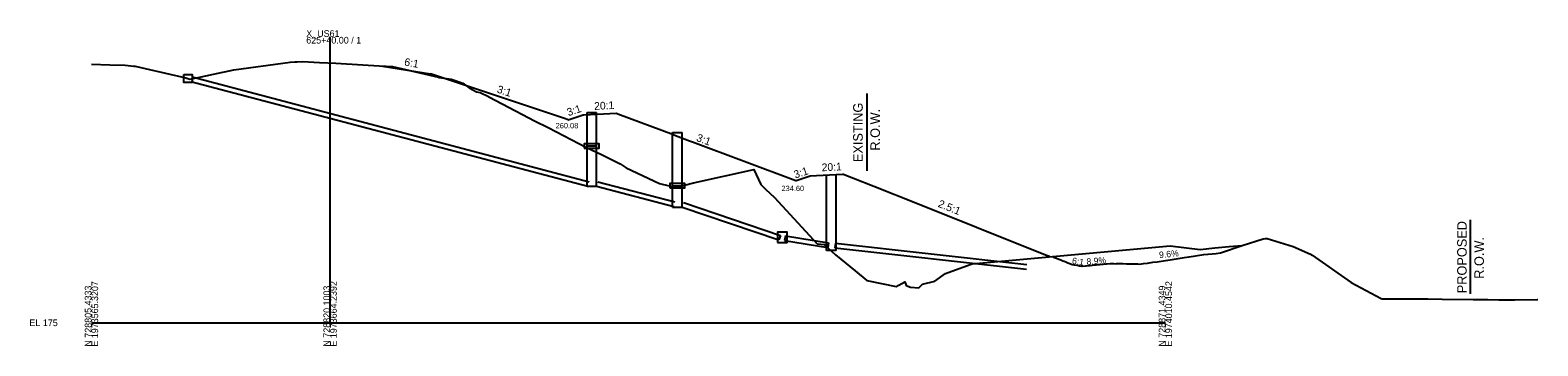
# Model space of a CAD drawing. Extents: x -26 to 630, y -39 to 9098.
# Drawn here: x -26 to 606, y 3490 to 3623 of the extents above; entities that cross this region are included whole.
import ezdxf

# ---------------------------------------------------------------- set-up
doc = ezdxf.new("R2010")
doc.units = 0
for name, color, linetype in [('CONST_DCH', 7, 'Continuous'), ('Default', 7, 'Continuous'), ('Draft_XS_Grid', 7, 'Continuous'), ('DTM_X_FLOW_ARROWS', 7, 'Continuous'), ('DTM_X_GROUND', 7, 'Continuous'), ('X_DTM_CONTOURS_MAJOR', 7, 'Continuous'), ('XS_CELL', 7, 'Continuous'), ('XS_P_DRAINAGE', 7, 'Continuous'), ('XS_P_GROUND', 7, 'Continuous'), ('XS_P_ROW', 7, 'Continuous'), ('XS_P_TX_DCH', 7, 'Continuous'), ('XS_P_TX_FS_BS', 7, 'Continuous'), ('XS_X_DRAINAGE', 7, 'Continuous'), ('XS_X_ROW', 7, 'Continuous')]:
    doc.layers.add(name, color=color, linetype=linetype)

msp = doc.modelspace()

# ---------------------------------------------------------------- linework, layer by layer
at = {"layer": 'DTM_X_GROUND'}
msp.add_lwpolyline([(0, 3608.6), (0.08, 3608.6), (7.63, 3608.32), (14.14, 3608.09), (17.77, 3607.77), (18.26, 3607.73), (22.45, 3606.73), (39.49, 3602.78), (41.19, 3602.23), (44.75, 3602.99), (51.16, 3604.35), (59.69, 3606.16), (83.26, 3609.39), (85.24, 3609.56), (86.23, 3609.58), (88.53, 3609.64), (95.49, 3609.29), (102.44, 3608.93), (122.82, 3607.7), (123.39, 3607.67), (123.52, 3607.66), (126.07, 3607.6), (129.7, 3606.68), (145.37, 3603.06), (145.43, 3603.03), (145.67, 3603.02), (150.72, 3602.29), (151.57, 3601.99), (152.45, 3601.67), (153.29, 3601.37), (153.95, 3601.13), (154.49, 3600.94), (154.79, 3600.83), (155.34, 3600.63), (155.58, 3600.55), (158.25, 3598.64), (161.31, 3596.96), (162.88, 3596.69), (166.36, 3594.97), (166.54, 3594.89), (183.33, 3585.99), (185.59, 3584.82), (191.42, 3581.9), (207.41, 3573.64), (213.7, 3570.65), (221.51, 3566.72), (223.98, 3565), (238.07, 3558.47), (242.09, 3557.45), (243.18, 3557.22), (244.66, 3556.84), (252.33, 3558.72), (277.57, 3564.38), (280.48, 3558.05), (282.44, 3556.15), (286.26, 3552.63), (304.1, 3533.11), (307.01, 3532.84), (311.83, 3528.55), (319.96, 3521.82), (324.91, 3517.73), (337.14, 3515.29), (338.15, 3515.8), (338.22, 3515.84), (338.24, 3515.85), (340.84, 3517.16), (341.37, 3515.61), (343.24, 3514.98), (346.64, 3514.73), (348.16, 3516.28), (353.32, 3517.47), (357.8, 3520.72), (368.2, 3524.5), (369.01, 3524.79), (451.99, 3532.32), (464.55, 3530.78), (470.72, 3531.52), (476.75, 3532.04), (482.1, 3532.49), (490.95, 3535.23), (491.91, 3535.4), (492.16, 3535.42), (492.62, 3535.33), (503.58, 3532.03), (510.84, 3528.79), (510.9, 3528.77), (511.2, 3528.51), (511.45, 3528.35), (527.81, 3516.91), (540.47, 3510.25), (540.79, 3510.09), (540.93, 3510), (541.09, 3510), (554.64, 3510), (559.95, 3509.99), (565.94, 3509.96), (579.02, 3509.81), (585.16, 3509.75), (589.74, 3509.7), (596.43, 3509.67), (605.83, 3509.73), (606.06, 3509.72)], dxfattribs=at)
at = {"layer": 'XS_CELL'}
for p, q in [((100, 3500), (100, 3620)), ((0, 3500), (100, 3500)), ((100, 3500), (450, 3500))]:
    msp.add_line(p, q, dxfattribs=at)
at = {"layer": 'XS_P_DRAINAGE'}
for p, q in [((207.64, 3574.23), (207.64, 3588.26)), ((207.64, 3588.26), (211.64, 3588.26)), ((211.64, 3574.23), (211.64, 3588.26)), ((243.49, 3557.52), (243.49, 3579.83)), ((243.49, 3579.83), (247.49, 3579.83)), ((247.49, 3557.52), (247.49, 3579.83)), ((308, 3530.4), (308, 3562.19)), ((312, 3530.4), (312, 3562.19)), ((290.78, 3536.53), (290.46, 3534.56)), ((290.46, 3534.56), (308.5, 3531.64)), ((290.78, 3536.53), (308.82, 3533.62)), ((308.82, 3533.62), (308.5, 3531.64)), ((311.73, 3533.44), (311.51, 3531.45)), ((311.73, 3533.44), (392, 3524.51)), ((312, 3530.4), (308, 3530.4)), ((311.51, 3531.45), (391.78, 3522.52))]:
    msp.add_line(p, q, dxfattribs=at)
for points in [[(206.52, 3573.29), (212.75, 3573.29), (212.75, 3575.06), (206.52, 3575.06)], [(242.34, 3556.66), (248.57, 3556.66), (248.57, 3558.42), (242.34, 3558.42)], [(287.4, 3533.76), (291.45, 3533.76), (291.45, 3538.04), (287.4, 3538.04)]]:
    msp.add_lwpolyline(points, close=True, dxfattribs=at)
at = {"layer": 'XS_P_GROUND'}
for points in [[(122, 3607.75), (142, 3604.42)], [(401.49, 3527.74), (401.45, 3527.76), (399.77, 3528.43), (341.89, 3551.58), (332.06, 3555.51), (331.8, 3555.62), (315.45, 3562.16), (315.08, 3562.3), (314.74, 3562.28), (301.08, 3561.6), (295.23, 3559.65), (295.08, 3559.6), (251.81, 3575.84), (250.61, 3576.29), (244, 3578.77), (243.83, 3578.84), (220.52, 3587.59), (220, 3587.78), (206.35, 3587.1), (206, 3587.08), (200.15, 3585.13), (200, 3585.08), (198.57, 3585.56), (142, 3604.42)], [(415.03, 3523.8), (415.06, 3523.81), (415.06, 3523.81), (416.55, 3523.94), (416.76, 3523.96), (418.04, 3524.07), (418.45, 3524.11), (419.52, 3524.2), (420.15, 3524.26), (421.01, 3524.34), (421.85, 3524.41), (422.5, 3524.47), (423.54, 3524.56), (423.99, 3524.6), (425.24, 3524.71), (425.48, 3524.74), (426.93, 3524.86), (426.96, 3524.87), (427.19, 3524.89), (428.45, 3524.84), (428.46, 3524.84), (429.34, 3524.81), (429.44, 3524.82), (430.6, 3524.88), (430.64, 3524.88), (432.14, 3524.84), (432.2, 3524.84), (433.68, 3524.8), (433.76, 3524.8), (435.22, 3524.76), (435.32, 3524.76), (436.76, 3524.72), (436.88, 3524.72), (438.3, 3524.68), (438.39, 3524.68), (439.25, 3524.66), (440.84, 3524.86), (442.43, 3525.07), (444.76, 3525.4), (446.49, 3525.64), (450.1, 3526.17), (451.97, 3526.45), (457.93, 3527.36), (459.91, 3527.67), (466.09, 3528.6), (467.92, 3528.84), (469.58, 3528.99), (471.25, 3529.14), (473.06, 3529.3), (482.1, 3532.49), (482.1, 3532.49)], [(402.59, 3527.84), (403.1, 3527.63), (403.15, 3527.61), (404.42, 3527.1), (404.64, 3527.01), (405.73, 3526.57), (406.13, 3526.41), (407.01, 3526.05), (407.62, 3525.8), (408.27, 3525.54), (409.11, 3525.2), (409.5, 3525.04), (410.59, 3524.6), (410.68, 3524.57), (410.98, 3524.44), (411.79, 3524.32), (412.08, 3524.27), (412.88, 3524.14), (413.57, 3524.04), (413.96, 3523.97), (415.03, 3523.8)]]:
    msp.add_lwpolyline(points, dxfattribs=at)
at = {"layer": 'XS_P_ROW'}
msp.add_line((577.73, 3543.15), (577.73, 3512.14), dxfattribs=at)
at = {"layer": 'XS_X_DRAINAGE'}
for p, q in [((41.62, 3601.27), (208, 3557.29)), ((42.13, 3603.2), (208.51, 3559.22)), ((207.64, 3557.29), (207.64, 3574.23)), ((207.64, 3574.23), (211.64, 3574.23)), ((211.64, 3557.29), (211.64, 3574.23)), ((207.64, 3557.29), (211.64, 3557.29)), ((211.64, 3557.29), (244.02, 3548.85)), ((212.14, 3559.23), (244.4, 3550.81)), ((243.49, 3548.59), (243.49, 3557.52)), ((243.49, 3557.52), (247.49, 3557.52)), ((247.49, 3548.59), (247.49, 3557.52)), ((248.13, 3550.48), (288.65, 3536.65)), ((243.49, 3548.59), (247.49, 3548.59)), ((247.49, 3548.59), (288, 3534.76)), ((288.65, 3536.65), (288, 3534.76))]:
    msp.add_line(p, q, dxfattribs=at)
msp.add_lwpolyline([(38.76, 3604.22), (42.24, 3604.22), (42.24, 3600.9), (38.76, 3600.9)], close=True, dxfattribs=at)
at = {"layer": 'XS_X_ROW'}
msp.add_line((325, 3563.75), (325, 3596.23), dxfattribs=at)

# ---------------------------------------------------------------- texts
at = {"layer": 'CONST_DCH'}
msp.add_text('X', height=0.001, dxfattribs=at).set_placement((415.03, 3523.8))
msp.add_text('X', height=0.001, dxfattribs=at).set_placement((415.03, 3523.8))
at = {"layer": 'Default'}
for p in [(199.96, 3585.02), (295.05, 3559.54), (401.45, 3527.68)]:
    msp.add_text('X', height=0.12, dxfattribs=at).set_placement(p)
at = {"layer": 'Draft_XS_Grid'}
msp.add_text('-', height=0.0001, dxfattribs=at).set_placement((0, 3500))
at = {"layer": 'DTM_X_FLOW_ARROWS'}
msp.add_text('X', height=0.001, dxfattribs=at).set_placement((410.98, 3524.44))
at = {"layer": 'X_DTM_CONTOURS_MAJOR'}
for p in [(121.96, 3607.69), (141.96, 3604.36), (205.96, 3587.02), (219.96, 3587.72), (301.05, 3561.54), (315.05, 3562.24), (315.12, 3523.58)]:
    msp.add_text('X', height=0.12, dxfattribs=at).set_placement(p)
at = {"layer": 'XS_CELL'}
for s, p in [('X_US61', (90, 3620)), ('625+40.00 / 1', (90, 3617.2)), ('EL 175', (-26, 3498.6))]:
    msp.add_text(s, height=2.8, dxfattribs=at).set_placement(p)
for s, p in [('N 728805.4333', (0, 3490)), ('E 1973565.3207', (2.8, 3490)), ('N 728820.1003', (100, 3490)), ('E 1973664.2392', (102.8, 3490)), ('N 728871.4349', (450, 3490)), ('E 1974010.4542', (452.8, 3490))]:
    msp.add_text(s, height=2.8, rotation=90, dxfattribs=at).set_placement(p)
at = {"layer": 'XS_P_ROW'}
for s, p in [('EXISTING', (323.18, 3567.43)), ('R.O.W.', (330.38, 3572.27)), ('PROPOSED', (576.26, 3512.4)), ('R.O.W.', (583.46, 3518.47))]:
    msp.add_text(s, height=4, rotation=90, dxfattribs=at).set_placement(p)
at = {"layer": 'XS_P_TX_DCH'}
for s, p in [('260.08', (194.49, 3581.63)), ('234.60', (289.12, 3555.29))]:
    msp.add_text(s, height=2.25, dxfattribs=at).set_placement(p)
at = {"layer": 'XS_P_TX_FS_BS'}
for s, height, rotation, p in [('6:1', 3.24, 350.53768, (130.91, 3607.97)), ('3:1', 3.24, 341.56505, (169.64, 3596.71)), ('3:1', 3.24, 18.435, (199.84, 3586.68)), ('20:1', 3.24, 2.86246, (210.71, 3589.34)), ('3:1', 3.24, 339.41399, (253.18, 3576.42)), ('3:1', 3.24, 18.43502, (294.92, 3560.53)), ('20:1', 3.24, 2.86246, (306.05, 3563.58)), ('2.5:1', 3.24, 338.19858, (354.45, 3548.75)), ('6:1', 2.7, 351.03704, (410.72, 3524.79)), ('8.9%', 2.7, 5.09363, (417.07, 3524.29)), ('9.6%', 2.7, 5.46485, (447.48, 3527.13))]:
    msp.add_text(s, height=height, rotation=rotation, dxfattribs=at).set_placement(p)

doc.saveas('drawing.dxf')
